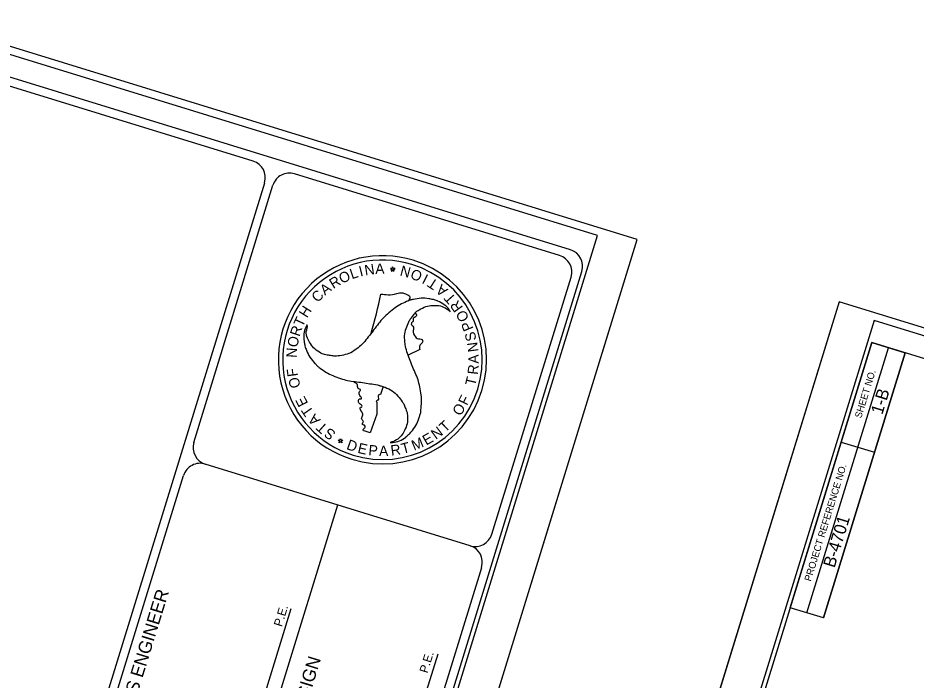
# Model space of a CAD drawing. Extents: x 1347947 to 1350662, y 1027710 to 1030532.
# Drawn here: x 1349137 to 1349655, y 1029589 to 1029971 of the extents above; entities that cross this region are included whole.
import ezdxf

# ---------------------------------------------------------------- set-up
doc = ezdxf.new("R2010")
doc.units = 0
for name, color, linetype in [('Sheet Cutting Line CELL', 7, 'Continuous'), ('Sheet Data Field CELL', 7, 'Continuous'), ('Sheet Plot Border Inside CELL', 7, 'Continuous'), ('Sheet Plot Border Outside CELL', 7, 'Continuous'), ('Sheet Symbology CELL', 7, 'Continuous'), ('Sheet Title CELL', 7, 'Continuous')]:
    doc.layers.add(name, color=color, linetype=linetype)

msp = doc.modelspace()

# ---------------------------------------------------------------- linework, layer by layer
at = {"layer": 'Sheet Cutting Line CELL'}
msp.add_line((1348998.14, 1028234.22), (1349493.77, 1029843.63), dxfattribs=at)
at = {"layer": 'Sheet Plot Border Inside CELL'}
msp.add_lwpolyline([(1348980.53, 1028253.25), (1349471, 1029845.94), (1348462.64, 1030156.47), (1347972.16, 1028563.78)], close=True, dxfattribs=at)
at = {"layer": 'Sheet Plot Border Outside CELL'}
msp.add_lwpolyline([(1348442.51, 1030167.38), (1347946.88, 1028557.97), (1348998.14, 1028234.22), (1349493.77, 1029843.63)], close=True, dxfattribs=at)
at = {"layer": 'Sheet Symbology CELL'}
for p, q in [((1349610.32, 1029807.71), (1349114.69, 1028198.29)), ((1349591.7, 1029628.2), (1349638.81, 1029781.15)), ((1349601.26, 1029625.25), (1349648.36, 1029778.2)), ((1349611.59, 1029726.75), (1349630.7, 1029720.86))]:
    msp.add_line(p, q, dxfattribs=at)
for points in [[(1350165.97, 1027874.54), (1350661.6, 1029483.96), (1349610.32, 1029807.71), (1349114.69, 1028198.29)], [(1350148.34, 1027893.58), (1350638.82, 1029486.26), (1349630.46, 1029796.8), (1349139.98, 1028204.11)], [(1349629.21, 1029784.1), (1349187.74, 1028350.54), (1350190.26, 1028041.81), (1350631.74, 1029475.37)], [(1349582.11, 1029631.15), (1349629.21, 1029784.1), (1349648.36, 1029778.2), (1349601.26, 1029625.25)]]:
    msp.add_lwpolyline(points, close=True, dxfattribs=at)
at = {"layer": 'Sheet Title CELL'}
for p, q in [((1348860.95, 1028519.22), (1349278.88, 1029876.33)), ((1349237.97, 1029726.5), (1349283.66, 1029874.86)), ((1349364.5, 1029831.57), (1349364.5, 1029831.57)), ((1349352.43, 1029826.87), (1349351.41, 1029826.82)), ((1349351.41, 1029826.82), (1349352.23, 1029826.23)), ((1349352.23, 1029826.23), (1349351.93, 1029825.24)), ((1349351.93, 1029825.24), (1349352.76, 1029825.88)), ((1349352.7, 1029827.85), (1349352.43, 1029826.87)), ((1349353.06, 1029826.87), (1349352.7, 1029827.85)), ((1349352.76, 1029825.88), (1349353.62, 1029825.3)), ((1349354.11, 1029826.86), (1349353.06, 1029826.87)), ((1349353.28, 1029826.24), (1349354.11, 1029826.86)), ((1349353.62, 1029825.3), (1349353.28, 1029826.24)), ((1349303.24, 1029794.28), (1349303.33, 1029794.14)), ((1349303.24, 1029794.28), (1349303.33, 1029794.14)), ((1349340.38, 1029789.56), (1349340.38, 1029789.56)), ((1349368.39, 1029780.03), (1349361.69, 1029776.83)), ((1349361.69, 1029776.83), (1349361.69, 1029776.83)), ((1349347.25, 1029758.76), (1349345.8, 1029754.24)), ((1349343.61, 1029749.66), (1349343.52, 1029742.85)), ((1349343.52, 1029742.85), (1349339.76, 1029732.09)), ((1349339.76, 1029732.09), (1349336.34, 1029733.27)), ((1349321.26, 1029727.83), (1349322.28, 1029727.89)), ((1349322.09, 1029727.28), (1349321.26, 1029727.83)), ((1349321.78, 1029726.27), (1349322.09, 1029727.28)), ((1349322.62, 1029726.89), (1349321.78, 1029726.27)), ((1349322.28, 1029727.89), (1349322.58, 1029728.87)), ((1349322.58, 1029728.87), (1349322.93, 1029727.87)), ((1349323.49, 1029726.3), (1349322.62, 1029726.89)), ((1349322.93, 1029727.87), (1349323.97, 1029727.89)), ((1349323.97, 1029727.89), (1349323.13, 1029727.25)), ((1349323.13, 1029727.25), (1349323.49, 1029726.3)), ((1349397.5, 1029666.91), (1349244.58, 1029714)), ((1349173.29, 1029516.47), (1349232.08, 1029707.39)), ((1349256.07, 1029479.57), (1349321.02, 1029690.46)), ((1349251.79, 1029492.81), (1349294.25, 1029630.67)), ((1349337.24, 1029469.38), (1349378.9, 1029604.61))]:
    msp.add_line(p, q, dxfattribs=at)
for points in [[(1349455.32, 1029837.69), (1348470.95, 1030140.83)], [(1349272.28, 1029888.83), (1348474.25, 1030134.58)], [(1349449.07, 1029834.38), (1349296.16, 1029881.47)], [(1349026.36, 1028410.74), (1349461.95, 1029825.18)], [(1349410, 1029673.53), (1349455.68, 1029821.88)], [(1349345.31, 1029463.49), (1349404.11, 1029654.42)]]:
    msp.add_lwpolyline(points, dxfattribs=at)
for centre, radius, start, end in [((1349269.28, 1029879.29), 10, 342.8834, 72.8834), ((1349293.17, 1029871.93), 10, 72.8834, 162.8834), ((1349346.83, 1029774.19), 60.05, 72.8711, 252.8711), ((1349446.08, 1029824.84), 10, 342.8834, 72.8834), ((1349452.34, 1029828.15), 10, 342.8834, 72.8834), ((1349346.83, 1029774.19), 57.54, 72.8711, 252.8711), ((1349346.83, 1029774.19), 60.05, 252.8711, 72.8711), ((1349346.83, 1029774.19), 57.54, 252.8711, 72.8711), ((1349036.06, 1029876.89), 316.6, 343.9887, 348.1947), ((1349036.06, 1029876.89), 316.6, 338.5496, 338.6492), ((1349247.53, 1029723.56), 10, 162.8834, 252.8834), ((1349241.64, 1029704.45), 10, 72.8834, 162.8834), ((1349400.39, 1029676.49), 10, 252.8834, 342.8834), ((1349394.5, 1029657.38), 10, 342.8834, 72.8834)]:
    msp.add_arc(centre, radius, start, end, dxfattribs=at)
for points in [[(1349385.98, 1029801.93), (1349385.33, 1029803.1), (1349382.51, 1029805.95), (1349378.79, 1029808.04), (1349378.42, 1029808.21), (1349376.23, 1029808.92), (1349373.58, 1029809.43), (1349369.12, 1029809.76), (1349364.66, 1029808.95), (1349362.79, 1029808.62), (1349360.8, 1029807.78), (1349356.8, 1029805.88), (1349353.33, 1029803.62), (1349349.66, 1029800.54), (1349346.65, 1029797.61), (1349343.92, 1029794.19), (1349341.29, 1029790.71), (1349338.66, 1029787.43), (1349335.85, 1029783.99), (1349332.74, 1029781.1), (1349332.43, 1029780.87), (1349328.53, 1029778.27), (1349324.34, 1029776.92), (1349320.27, 1029776.35), (1349318.21, 1029776.39), (1349315.68, 1029776.8), (1349314.2, 1029776.97), (1349311.37, 1029778.07), (1349307.84, 1029780.43), (1349305.3, 1029783.5), (1349303.56, 1029786.74), (1349302.91, 1029790.42), (1349303.33, 1029794.14), (1349303.24, 1029794.28)], [(1349362.04, 1029808.38), (1349360.8, 1029807.78), (1349356.8, 1029805.88), (1349353.33, 1029803.62), (1349349.66, 1029800.54), (1349346.65, 1029797.61), (1349343.92, 1029794.19), (1349341.29, 1029790.71), (1349340.38, 1029789.56)], [(1349345.96, 1029812.11), (1349350.04, 1029811.74), (1349355.17, 1029812.36), (1349358.03, 1029812.89), (1349360.15, 1029812.2), (1349362.53, 1029810.93), (1349362.03, 1029808.4)], [(1349351.37, 1029726.43), (1349352.79, 1029726.44), (1349356.64, 1029727.47), (1349360.32, 1029729.61), (1349360.59, 1029729.88), (1349362.38, 1029731.4), (1349364.09, 1029733.44), (1349366.62, 1029737.17), (1349368.14, 1029741.39), (1349368.79, 1029743.19), (1349369.06, 1029745.39), (1349369.39, 1029749.72), (1349369.19, 1029753.85), (1349368.36, 1029758.61), (1349367.35, 1029762.64), (1349365.72, 1029766.72), (1349364, 1029770.75), (1349362.49, 1029774.72), (1349360.98, 1029778.82), (1349359.97, 1029782.98), (1349359.94, 1029783.42), (1349359.65, 1029788.05), (1349360.56, 1029792.32), (1349362.09, 1029796.09), (1349363.14, 1029797.98), (1349364.79, 1029799.88), (1349365.67, 1029801.12), (1349368.03, 1029803.02), (1349371.81, 1029804.85), (1349375.75, 1029805.53), (1349379.46, 1029805.43), (1349382.96, 1029804.17), (1349385.98, 1029801.93)], [(1349361.69, 1029776.83), (1349360.98, 1029778.82), (1349359.97, 1029782.98), (1349359.94, 1029783.42), (1349359.65, 1029788.05), (1349360.56, 1029792.32), (1349362.09, 1029796.09), (1349363.14, 1029797.98), (1349364.79, 1029799.88), (1349365.62, 1029801.02)], [(1349365.63, 1029801), (1349366.47, 1029800.16), (1349366.28, 1029799.27), (1349364.6, 1029798.13), (1349364.4, 1029796.16), (1349363.65, 1029795.46), (1349363.46, 1029794.91), (1349364.73, 1029793.04), (1349364.57, 1029791.08), (1349365.85, 1029787.43), (1349366.93, 1029786.42), (1349369.76, 1029785.8), (1349370.08, 1029784.9), (1349369.67, 1029784.05), (1349368.39, 1029782.44), (1349368.39, 1029780.03)], [(1349303.33, 1029794.14), (1349302.59, 1029792.96), (1349301.57, 1029789.1), (1349301.62, 1029784.84), (1349301.7, 1029784.44), (1349302.12, 1029782.19), (1349303.02, 1029779.66), (1349305, 1029775.64), (1349307.89, 1029772.14), (1349309.14, 1029770.71), (1349310.83, 1029769.43), (1349314.49, 1029766.9), (1349318.2, 1029765.03), (1349322.69, 1029763.37), (1349326.73, 1029762.2), (1349331.03, 1029761.6), (1349335.38, 1029761.04), (1349339.58, 1029760.4), (1349343.89, 1029759.69), (1349347.99, 1029758.44), (1349348.34, 1029758.31), (1349352.49, 1029756.23), (1349355.77, 1029753.29), (1349358.28, 1029750.02), (1349359.35, 1029748.22), (1349360.25, 1029745.83), (1349360.79, 1029744.48), (1349361.31, 1029741.47), (1349361.02, 1029737.25), (1349359.61, 1029733.48), (1349357.7, 1029730.34), (1349354.85, 1029727.94), (1349351.37, 1029726.43)], [(1349330.92, 1029761.61), (1349331.03, 1029761.6), (1349335.38, 1029761.04), (1349339.58, 1029760.4), (1349343.89, 1029759.69), (1349347.25, 1029758.74)], [(1349336.34, 1029733.27), (1349335.98, 1029733.26), (1349335.79, 1029733.95), (1349336.95, 1029735.36), (1349336.5, 1029736.39), (1349335.8, 1029736.57), (1349335.3, 1029737.43), (1349335.86, 1029738.47), (1349334.89, 1029739.87), (1349334.96, 1029740.85), (1349335.55, 1029742.79), (1349333.95, 1029745.8), (1349334.11, 1029746.81), (1349334.8, 1029746.86), (1349335.1, 1029747.42), (1349333.5, 1029749), (1349333.3, 1029749.33), (1349333.15, 1029751.36), (1349333.63, 1029751.73), (1349334.52, 1029751.6), (1349334.77, 1029751.81), (1349334.53, 1029752.53), (1349333.76, 1029753.65), (1349333.45, 1029755.36), (1349334.17, 1029756.98), (1349332.88, 1029757.7), (1349332.16, 1029760.08), (1349331.49, 1029760.73), (1349330.71, 1029761.09)], [(1349345.8, 1029754.24), (1349344.83, 1029754.05), (1349344.31, 1029753.24), (1349344.57, 1029751.86), (1349344.24, 1029750.97), (1349343.22, 1029750.21), (1349343.61, 1029749.66)]]:
    msp.add_spline(points, degree=3, dxfattribs=at)

# ---------------------------------------------------------------- texts
at = {"layer": 'Sheet Data Field CELL'}
for s, p in [('1-B', (1349635.22, 1029742.17)), ('B-4701', (1349607.67, 1029653.76))]:
    msp.add_text(s, height=7.088, rotation=72.8834, dxfattribs=at).set_placement(p)
at = {"layer": 'Sheet Symbology CELL'}
for s, height, p in [('SHEET NO.', 4, (1349623.06, 1029740.21)), ('PROJECT REFERENCE NO.', 4.0001, (1349593.99, 1029646.08))]:
    msp.add_text(s, height=height, rotation=72.8834, dxfattribs=at).set_placement(p)
at = {"layer": 'Sheet Title CELL'}
for s, height, rotation, p in [('N', 5.98, 8.7664, (1349336.94, 1029822.82)), ('A', 5.99, 1.3345, (1349342.75, 1029823.68)), ('O', 6, 24.6896, (1349323.36, 1029817.94)), ('L', 5.97, 18.4559, (1349329.16, 1029820.6)), ('I', 6, 14.4665, (1349334.1, 1029822.13)), ('N', 5.99, 165.0792, (1349363.69, 1029827.26)), ('O', 5.97, 157.8312, (1349370.41, 1029824.59)), ('R', 5.98, 31.8092, (1349318.49, 1029814.93)), ('I', 6, 152.6956, (1349373.84, 1029822.86)), ('T', 5.98, 147.0457, (1349379.53, 1029819.21)), ('C', 5.97, 45.6702, (1349309.47, 1029806.87)), ('A', 5.98, 38.1731, (1349313.67, 1029811.13)), ('A', 6, 139.9613, (1349385.02, 1029814.71)), ('T', 5.97, 131.8742, (1349389.63, 1029809.73)), ('R', 6, 125.7744, (1349393.57, 1029804.4)), ('H', 5.98, 58.0125, (1349303.26, 1029797.98)), ('T', 6, 65.0972, (1349300.76, 1029792.68)), ('O', 6, 118.5853, (1349397.08, 1029798.07)), ('R', 5.99, 71.7469, (1349298.97, 1029787.24)), ('P', 5.98, 111.8933, (1349399.52, 1029792.14)), ('O', 6, 78.3568, (1349297.69, 1029781.04)), ('S', 5.96, 104.7015, (1349401.23, 1029785.74)), ('N', 5.97, 97.491, (1349402.24, 1029779.04)), ('N', 5.99, 85.8549, (1349297.23, 1029775.2)), ('A', 5.97, 90.4594, (1349402.41, 1029771.97)), ('F', 6, 97.9418, (1349298.11, 1029764.82)), ('R', 5.99, 83.7063, (1349401.78, 1029765.39)), ('O', 5.99, 105.0887, (1349299.72, 1029758.7)), ('T', 5.97, 76.7496, (1349400.3, 1029758.77)), ('E', 5.97, 117.028, (1349304.08, 1029749.01)), ('F', 5.98, 63.8404, (1349395.62, 1029747.45)), ('T', 5.97, 124.1437, (1349307.35, 1029744.15)), ('O', 5.98, 56.6752, (1349391.72, 1029741.35)), ('A', 6.01, 131.1989, (1349311.42, 1029739.48)), ('T', 6, 138.2512, (1349315.73, 1029735.53)), ('N', 6, 36.5295, (1349377.65, 1029727.9)), ('T', 5.98, 43.3715, (1349383.04, 1029731.97)), ('S', 5.98, 144.6274, (1349320.37, 1029732.22)), ('E', 5.97, 29.558, (1349372.07, 1029724.65)), ('D', 5.99, 340.7241, (1349325.66, 1029722.77)), ('E', 5.96, 347.012, (1349332.16, 1029720.56)), ('P', 5.99, 354.5444, (1349338.53, 1029719.21)), ('R', 5.99, 8.2056, (1349351.99, 1029718.83)), ('T', 5.98, 14.8561, (1349358.52, 1029719.83)), ('M', 5.97, 22.0912, (1349365.06, 1029721.67)), ('A', 5.98, 1.137, (1349344.9, 1029718.61)), (' HYDRAULICS ENGINEER', 7.5, 72.8834, (1349187.68, 1029523.23)), ('P.E.', 5, 72.8834, (1349288.77, 1029619.84)), ('ROADWAY DESIGN', 7.4994, 72.8834, (1349284.06, 1029512.8)), ('P.E.', 5, 72.8834, (1349372.81, 1029593.04))]:
    msp.add_text(s, height=height, rotation=rotation, dxfattribs=at).set_placement(p)

doc.saveas('drawing.dxf')
